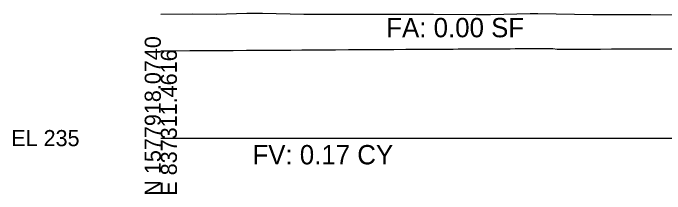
# Model space of a CAD drawing. Extents: x -26 to 303, y -16 to 6048.
# Drawn here: x -25.7 to 87.7, y 4990.3 to 5021.7 of the extents above; entities that cross this region are included whole.
import ezdxf

# ---------------------------------------------------------------- set-up
doc = ezdxf.new("R2010")
doc.units = 0
for name, color, linetype in [('Draft_XS_Grid', 7, 'Continuous'), ('DTM_X_GROUND', 7, 'Continuous'), ('XS_CELL', 7, 'Continuous'), ('XS_P_GROUND', 7, 'Continuous'), ('XS_SHEET_EW_TX_AREA', 7, 'Continuous'), ('XS_SHEET_EW_TX_VOLUME', 7, 'Continuous')]:
    doc.layers.add(name, color=color, linetype=linetype)

msp = doc.modelspace()

# ---------------------------------------------------------------- linework, layer by layer
at = {"layer": 'DTM_X_GROUND'}
msp.add_lwpolyline([(0, 5021.54), (5.57, 5021.55), (9.6, 5021.53), (14.93, 5021.7), (17.68, 5021.7), (24.89, 5021.54), (27.64, 5021.53), (34.53, 5021.52), (37.54, 5021.52), (44.68, 5021.5), (47.44, 5021.5), (54.83, 5021.48), (57.34, 5021.48), (64.22, 5021.64), (65.53, 5021.64), (75.13, 5021.45), (77, 5021.45), (83.39, 5021.43), (85.19, 5021.43), (93.24, 5021.34)], dxfattribs=at)
msp.add_lwpolyline([(0, 5021.54), (5.57, 5021.55), (9.6, 5021.53), (14.93, 5021.7), (17.68, 5021.7), (24.89, 5021.54), (27.64, 5021.53), (34.53, 5021.52), (37.54, 5021.52), (44.68, 5021.5), (47.44, 5021.5), (54.83, 5021.48), (57.34, 5021.48), (64.22, 5021.64), (65.53, 5021.64), (75.13, 5021.45), (77, 5021.45), (83.39, 5021.43), (85.19, 5021.43), (93.24, 5021.34)], dxfattribs=at)
at = {"layer": 'XS_CELL'}
msp.add_line((0, 5000), (150, 5000), dxfattribs=at)
at = {"layer": 'XS_P_GROUND'}
for points in [[(0, 5015.16), (0.21, 5015.16), (0.45, 5015.16), (2.62, 5015.17), (5.06, 5015.19), (5.16, 5015.19), (5.27, 5015.19), (7.63, 5015.2), (10.08, 5015.22), (10.1, 5015.22), (10.13, 5015.22), (12.57, 5015.23), (14.9, 5015.24), (15.05, 5015.25), (15.19, 5015.25), (16.75, 5015.26), (18.16, 5015.26), (18.99, 5015.27), (19.72, 5015.27), (20.01, 5015.28), (20.25, 5015.28), (22.62, 5015.29), (24.54, 5015.3), (24.73, 5015.3), (24.88, 5015.31), (25.12, 5015.31), (25.31, 5015.31), (27.63, 5015.32), (29.35, 5015.33), (29.95, 5015.34), (30.37, 5015.34), (32.64, 5015.35), (34.17, 5015.36), (34.94, 5015.37), (35.43, 5015.37), (37.64, 5015.38), (38.99, 5015.39), (39.94, 5015.4), (40.5, 5015.4), (42.62, 5015.41), (43.8, 5015.42), (44.95, 5015.43), (45.56, 5015.43), (45.63, 5015.43), (46.62, 5015.44), (48.62, 5015.45), (49.29, 5015.45), (50.62, 5015.46), (50.69, 5015.46), (50.85, 5015.46), (51.71, 5015.47), (53.43, 5015.48), (54.16, 5015.48), (55.68, 5015.49), (56.49, 5015.5), (58.25, 5015.51), (59.01, 5015.51), (60.74, 5015.52), (61.59, 5015.53), (63.06, 5015.54), (63.54, 5015.54)], [(63.54, 5015.54), (64.87, 5015.55), (65.79, 5015.55), (66.36, 5015.56), (67.88, 5015.57), (68.16, 5015.53), (68.94, 5015.41), (69.2, 5015.41), (69.96, 5015.42), (70.18, 5015.42), (70.85, 5015.42), (72.13, 5015.43), (75.91, 5015.45), (76.45, 5015.46), (78.35, 5015.47), (78.89, 5015.47), (80.97, 5015.48), (81.94, 5015.48), (86.03, 5015.49), (88.36, 5015.49), (90.44, 5015.49), (91, 5015.49), (91.01, 5015.49)]]:
    msp.add_lwpolyline(points, dxfattribs=at)

# ---------------------------------------------------------------- texts
at = {"layer": 'Draft_XS_Grid'}
msp.add_text('-', height=0.0001, dxfattribs=at).set_placement((0, 5000))
at = {"layer": 'XS_CELL'}
for s, p in [('N 1577918.0740', (0, 4990)), ('E 837311.4616', (2.8, 4990))]:
    msp.add_text(s, height=2.8, rotation=90, dxfattribs=at).set_placement(p)
msp.add_text('EL 235', height=2.8, dxfattribs=at).set_placement((-26, 4998.6))
at = {"layer": 'XS_SHEET_EW_TX_AREA'}
msp.add_text('FA: 0.00 SF', height=3.36, dxfattribs=at).set_placement((39.2, 5017.5))
at = {"layer": 'XS_SHEET_EW_TX_VOLUME'}
msp.add_text('FV: 0.17 CY', height=3.36, dxfattribs=at).set_placement((15.93, 4995.44))

doc.saveas('drawing.dxf')
